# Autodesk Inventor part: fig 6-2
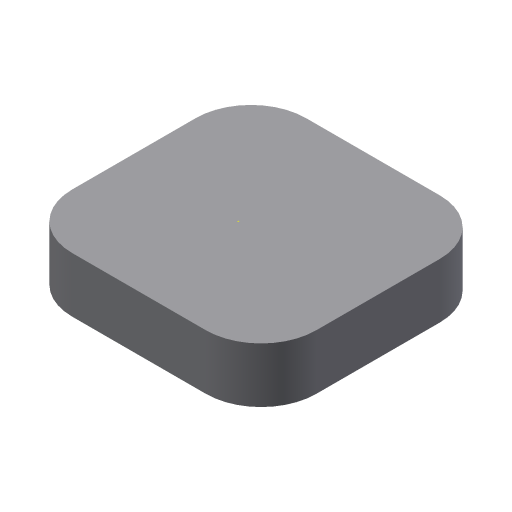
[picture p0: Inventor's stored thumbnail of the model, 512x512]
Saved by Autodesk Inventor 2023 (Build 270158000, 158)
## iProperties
Created: 2004-05
Part Number: fig 6-2
Document SubType Name: Modeling
Designer: CADCIM Technologies
Manufacturer: Standard
Standards Organization: Custom
Density: 1 g/cm^3
Material: Generic
Appearance: Default
Author: CADCIM Technologies
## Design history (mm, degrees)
sketch "Sketch1"
  geometry: L1 (0, 0)-(44.293, 0); L2 (44.293, 0)-(44.293, 42.442); L3 (44.293, 42.442)-(0, 42.442); L4 (0, 42.442)-(0, 0)
  constraints: 8 end point, 2 parallel, 1 horizontal, 1 perpendicular
extrude "Extrusion1" new body sketch "Sketch1" distance "d0" = 10; taper "d1" = 0 deg
fillet "Fillet1" dims "d2" = 10
sketch "Sketch2"
  geometry: 1 further point
sketch "Sketch3"
  geometry: L1 (10, 42.442)-(34.293, 42.442) reference; L2 (0, 10)-(0, 32.442) reference; L3 (34.293, 0)-(10, 0) reference; L4 (44.293, 32.442)-(44.293, 10) reference; A1 r 10 centre (34.293, 32.442) between (44.293, 32.442) and (34.293, 42.442) reference; A2 r 10 centre (10, 32.442) between (10, 42.442) and (0, 32.442) reference; A3 r 10 centre (10, 10) between (0, 10) and (10, 0) reference; A4 r 10 centre (34.293, 10) between (34.293, 0) and (44.293, 10) reference; 1 further point
workpoint "Work Point1"
body "Solid1"
